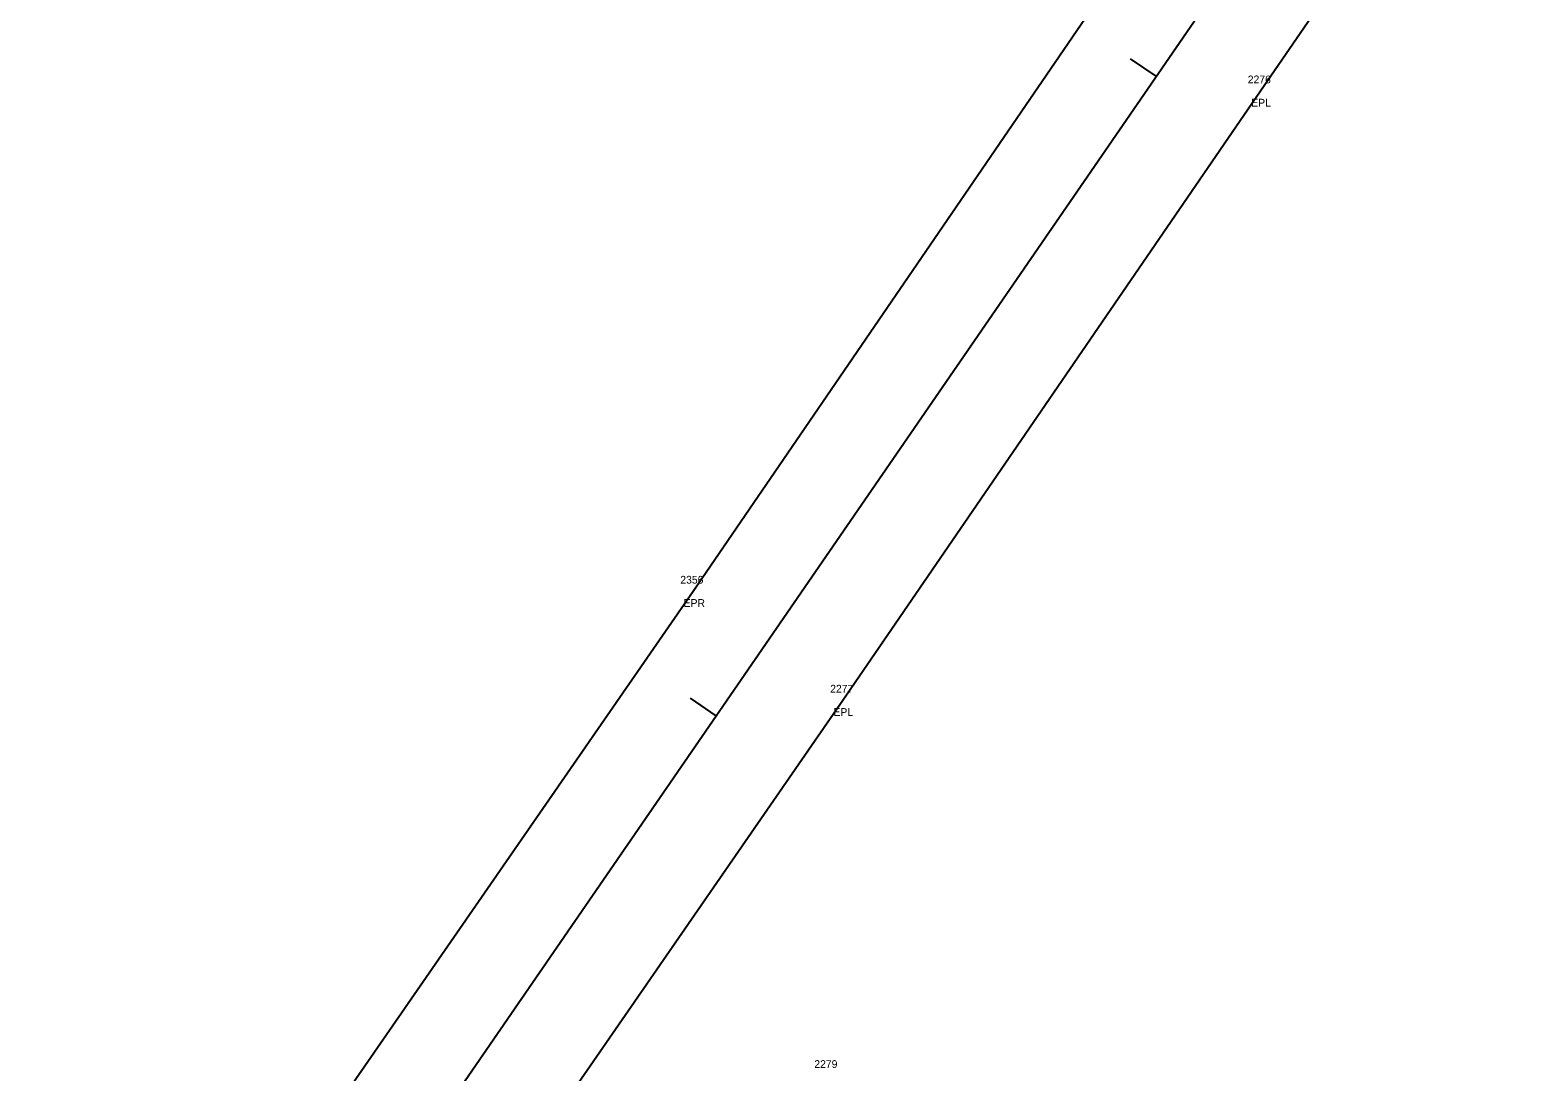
# Model space of a CAD drawing. Extents: x 2266664 to 2272542, y 716533 to 724777.
# Drawn here: x 2271573.7 to 2271767.8, y 723701.7 to 723835.9 of the extents above; entities that cross this region are included whole.
import ezdxf

# ---------------------------------------------------------------- set-up
doc = ezdxf.new("R2010")
doc.units = 0
for name, color, linetype in [('RD_EX_Road', 7, 'Continuous'), ('RD_EX_Road_txCode', 7, 'Continuous'), ('RD_EX_VEG_txCode', 7, 'Continuous'), ('RD_HC_Cl', 7, 'Continuous'), ('RD_HC_Data_Tic', 7, 'Continuous'), ('RD_SMD_Locator', 7, 'Continuous')]:
    doc.layers.add(name, color=color, linetype=linetype)

msp = doc.modelspace()

# ---------------------------------------------------------------- linework, layer by layer
at = {"layer": 'RD_EX_Road'}
for points in [[(2272350.52, 724770.05), (2272301.75, 724698.9), (2272265.2, 724646.02), (2272253.02, 724627.92), (2272200.51, 724550.87), (2272147.54, 724474.34), (2272126.28, 724443.66), (2272107.36, 724416.48), (2272092.2, 724393.69), (2272038.42, 724315.2), (2271991.52, 724247.47), (2271974.41, 724222.16), (2271928.73, 724155.87), (2271879.39, 724084.16), (2271852.9, 724045.63), (2271818.37, 723996.02), (2271765.12, 723918.77), (2271712.35, 723841.58), (2271659.05, 723763.61), (2271604.53, 723684.77), (2271550.65, 723606.61)], [(2272368.97, 724754.13), (2272346.57, 724721.92), (2272321.77, 724685.09), (2272273.25, 724614.42), (2272223.01, 724540.91), (2272206.83, 724517.64), (2272178.6, 724477.03), (2272166.48, 724459.37), (2272137.67, 724416.89), (2272108.53, 724374.93), (2272057.89, 724300.99), (2272036.24, 724269.85), (2272022.13, 724249.17), (2272003.16, 724221.27), (2271948.47, 724142.38), (2271900.7, 724072.99), (2271873.7, 724033.58), (2271837.94, 723981.87), (2271784.96, 723904.95), (2271732.12, 723828.06), (2271678.32, 723749.57), (2271627.92, 723676.62), (2271614.21, 723655.35), (2271570.62, 723593.07)]]:
    msp.add_lwpolyline(points, dxfattribs=at)
at = {"layer": 'RD_HC_Cl'}
msp.add_line((2267342.91, 717471.2), (2272360.46, 724762.59), dxfattribs=at)
at = {"layer": 'RD_HC_Data_Tic'}
for p, q in [((2271718.68, 723829.97), (2271715.38, 723832.23)), ((2271661.99, 723747.59), (2271658.69, 723749.85))]:
    msp.add_line(p, q, dxfattribs=at)
at = {"layer": 'RD_SMD_Locator'}
for centre in [(2271732.12, 723828.06), (2271659.05, 723763.61), (2271678.32, 723749.57)]:
    msp.add_circle(centre, 0.001, dxfattribs=at)

# ---------------------------------------------------------------- texts
at = {"layer": 'RD_EX_Road_txCode'}
for s, p in [('2276', (2271730.47, 723829.06)), ('EPL', (2271730.92, 723826.06)), ('2356', (2271657.39, 723764.61)), ('EPR', (2271657.82, 723761.61)), ('2277', (2271676.69, 723750.57)), ('EPL', (2271677.12, 723747.57))]:
    msp.add_text(s, height=1, dxfattribs=at).set_placement(p)
at = {"layer": 'RD_EX_VEG_txCode'}
msp.add_text('2279', height=1, dxfattribs=at).set_placement((2271674.65, 723702.22))

doc.saveas('drawing.dxf')
